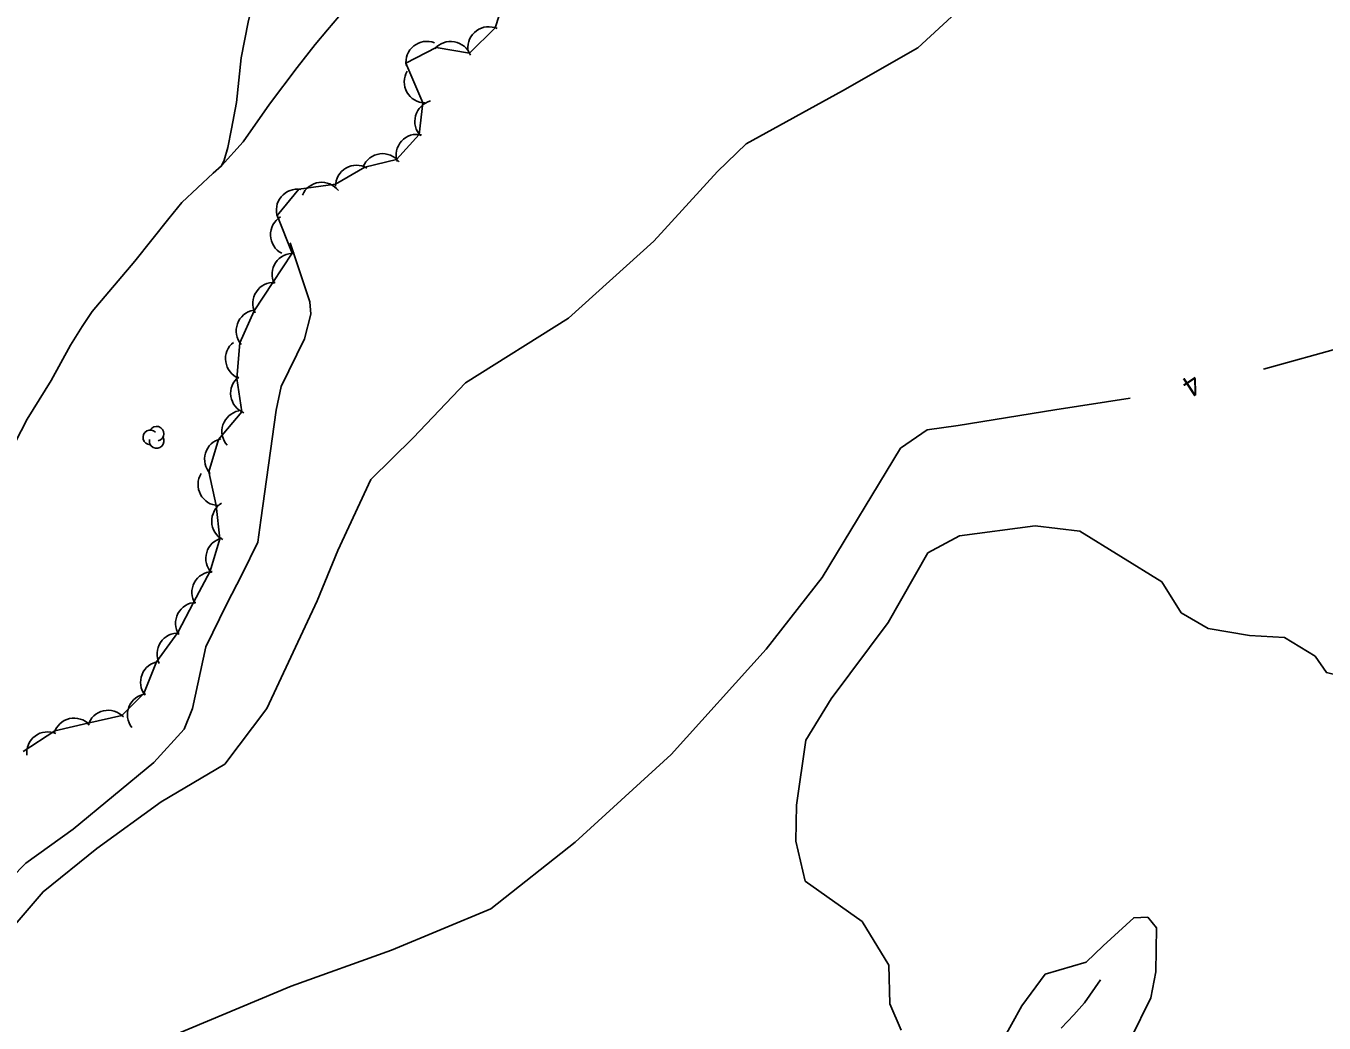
# Model space of a CAD drawing. Extents: x 643342 to 646936, y 5873857 to 5876103.
# Drawn here: x 644900.4 to 645086.4, y 5874417.3 to 5874560.2 of the extents above; entities that cross this region are included whole.
import ezdxf

# ---------------------------------------------------------------- set-up
doc = ezdxf.new("R2010")
doc.units = 0
for name, color, linetype in [('Niveau 2', 7, 'Continuous'), ('Niveau 22', 7, 'Continuous'), ('Niveau 44', 7, 'Continuous')]:
    doc.layers.add(name, color=color, linetype=linetype)

msp = doc.modelspace()

# ---------------------------------------------------------------- linework, layer by layer
at = {"layer": 'Niveau 2'}
for points in [[(645077.7, 5874510.97), (645089.39, 5874514.25), (645098.21, 5874521.23), (645104.55, 5874528.4), (645107.37, 5874537.11), (645109.34, 5874546.11), (645117.52, 5874564.17), (645122.1, 5874572.99), (645130.85, 5874588.01), (645134.74, 5874593.01), (645147.47, 5874604.86), (645154.32, 5874613.24), (645160.03, 5874620.96), (645165.88, 5874628.33), (645170.57, 5874631.23), (645172.38, 5874635.85), (645176.56, 5874643.59), (645182.1, 5874648.57)], [(645168.31, 5874573.93), (645168.27, 5874573.87), (645165.79, 5874571.46), (645159.02, 5874561.45), (645155.45, 5874553.41), (645153.44, 5874546.79), (645149.85, 5874539.11), (645145.87, 5874528.57), (645141.75, 5874521.8), (645134.17, 5874514.09), (645128.28, 5874500.6), (645120.31, 5874490.03), (645114.98, 5874478.69), (645111.19, 5874475.72), (645100.42, 5874471.57), (645088.62, 5874467.05), (645086.71, 5874467.51), (645085.08, 5874469.87), (645080.72, 5874472.53), (645075.7, 5874472.84)], [(645033.6, 5874562.02), (645028.16, 5874557.02), (645017.36, 5874550.84), (645003.58, 5874543.28), (644999.48, 5874539.32), (644990.35, 5874529.34), (644978.11, 5874518.31), (644963.38, 5874509.01), (644955.88, 5874501.15), (644949.79, 5874495.17), (644945.06, 5874485), (644942.13, 5874477.8), (644934.92, 5874462.37), (644928.86, 5874454.37), (644919.76, 5874449.01), (644910.52, 5874442.33), (644902.84, 5874436.11), (644893.32, 5874425.03), (644885.55, 5874412.64)], [(644862.96, 5874331.87), (644868.54, 5874343.25), (644872.82, 5874351.35), (644878.62, 5874361.34), (644883.65, 5874370.44), (644890.35, 5874381.08), (644898.02, 5874394.74), (644909.58, 5874408.43), (644919.08, 5874414.52), (644938.37, 5874422.59), (644952.78, 5874427.72), (644967.01, 5874433.66), (644979.09, 5874443.24), (644992.85, 5874455.77), (645006.44, 5874470.89), (645014.46, 5874481.14), (645025.68, 5874499.65), (645029.5, 5874502.27), (645033.94, 5874502.93), (645047.82, 5874505.17), (645058.6, 5874506.84)], [(645024.03, 5874425.61), (645020.19, 5874431.84), (645012.01, 5874437.65), (645010.67, 5874443.34), (645010.78, 5874448.54), (645012.14, 5874457.85), (645015.73, 5874463.76), (645023.92, 5874474.71), (645029.59, 5874484.66), (645034.13, 5874487.1), (645044.98, 5874488.54), (645051.39, 5874487.79), (645063.13, 5874480.5), (645065.91, 5874476.09), (645069.77, 5874473.81), (645075.7, 5874472.84)], [(645040.11, 5874414.44), (645043.09, 5874419.78), (645046.43, 5874424.31), (645052.31, 5874426.01), (645054.74, 5874428.36), (645059.11, 5874432.38), (645061.1, 5874432.45), (645062.38, 5874430.95), (645062.29, 5874424.63), (645061.54, 5874420.93), (645058.66, 5874415.01)], [(645024.03, 5874425.61), (645024.18, 5874420.07), (645025.8, 5874416.29)]]:
    msp.add_lwpolyline(points, dxfattribs=at)
at = {"layer": 'Niveau 22'}
for points in [[(644898.02, 5874498.92), (644900.58, 5874503.83), (644903.98, 5874509.35), (644906.78, 5874514.43), (644908.44, 5874517.12), (644909.89, 5874519.24), (644916.01, 5874526.45), (644920.84, 5874532.57), (644922.72, 5874534.87), (644927.21, 5874539.05), (644928.41, 5874540.13), (644928.79, 5874540.94), (644929.33, 5874542.75), (644929.86, 5874545.4), (644930.55, 5874549.19), (644931.23, 5874555.58), (644932.21, 5874560.72), (644932.77, 5874562.92), (644934.55, 5874567.88), (644935.58, 5874570.37), (644937.65, 5874574.06)], [(644945.21, 5874561.49), (644943.59, 5874559.6), (644941.84, 5874557.5), (644939.24, 5874554.2), (644935.28, 5874548.94), (644931.53, 5874543.54), (644928.41, 5874540.13)], [(644872.15, 5874408.35), (644881.75, 5874419.98), (644889.76, 5874429.22), (644894.01, 5874433.74), (644900.35, 5874440.23), (644907.17, 5874445.09), (644918.71, 5874454.64), (644923.06, 5874459.41), (644924.24, 5874462.36), (644926.15, 5874471.2), (644929.1, 5874477.28), (644931.36, 5874481.63), (644933.6, 5874486.22), (644934.06, 5874489.35), (644936.25, 5874505.12), (644936.93, 5874508.5), (644940.29, 5874515.33), (644941.2, 5874518.86), (644941.06, 5874520.63), (644938.24, 5874529.1)], [(645054.32, 5874423.49), (645052.05, 5874420.18), (645050.54, 5874418.49), (645048.7, 5874416.59)]]:
    msp.add_lwpolyline(points, dxfattribs=at)
at = {"layer": 'Niveau 44'}
for points in [[(644969.29, 5874565.07), (644967.63, 5874559.89), (644963.94, 5874556.26), (644959.16, 5874557.09), (644954.82, 5874554.81), (644957.23, 5874549.14), (644956.74, 5874544.61), (644953.47, 5874541.03), (644948.96, 5874539.94), (644944.76, 5874537.51), (644939.46, 5874536.77), (644936.36, 5874533.02), (644938.53, 5874527.58), (644935.77, 5874523.41), (644933.09, 5874519.36), (644931.03, 5874514.77)], [(644931.03, 5874514.77), (644930.61, 5874509.67), (644931.33, 5874504.87), (644927.98, 5874500.91), (644926.59, 5874496.26), (644927.63, 5874491.47), (644928.15, 5874486.69), (644926.79, 5874482.04), (644924.4, 5874477.54), (644922.13, 5874473.25), (644919.09, 5874469.03), (644917.27, 5874464.53), (644914.13, 5874461.38), (644909.26, 5874460.26), (644904.53, 5874459.16), (644899.98, 5874456.21)]]:
    msp.add_lwpolyline(points, dxfattribs=at)
for centre, radius, start, end in [((644966.69, 5874557.04), 3, 65.8041, 185.7821), ((644966.69, 5874557.04), 3, 65.8041, 185.7821), ((644966.69, 5874557.04), 3, 65.8041, 185.7821), ((644957.82, 5874554.95), 3, 68.6819, 188.6598), ((644957.82, 5874554.95), 3, 68.6819, 188.6598), ((644957.82, 5874554.95), 3, 68.6819, 188.6598), ((644961.25, 5874554.94), 3, 20.1183, 140.0962), ((644961.25, 5874554.94), 3, 20.1183, 140.0962), ((644961.25, 5874554.94), 3, 20.1183, 140.0962), ((644957.59, 5874552.12), 3, 149.047, 269.0249), ((644957.59, 5874552.12), 3, 149.047, 269.0249), ((644957.59, 5874552.12), 3, 149.047, 269.0249), ((644959.1, 5874546.5), 3, 104.5199, 224.4978), ((644959.1, 5874546.5), 3, 104.5199, 224.4978), ((644959.1, 5874546.5), 3, 104.5199, 224.4978), ((644956.41, 5874541.63), 3, 77.6215, 197.5994), ((644956.41, 5874541.63), 3, 77.6215, 197.5994), ((644956.41, 5874541.63), 3, 77.6215, 197.5994), ((644951.47, 5874538.86), 3, 37.5157, 157.4936), ((644951.47, 5874538.86), 3, 37.5157, 157.4936), ((644951.47, 5874538.86), 3, 37.5157, 157.4936), ((644947.74, 5874537.2), 3, 60.0297, 180.0077), ((644947.74, 5874537.2), 3, 60.0297, 180.0077), ((644947.74, 5874537.2), 3, 60.0297, 180.0077), ((644939.27, 5874533.77), 3, 80.423, 200.4009), ((644939.27, 5874533.77), 3, 80.423, 200.4009), ((644939.27, 5874533.77), 3, 80.423, 200.4009), ((644942.76, 5874534.76), 3, 37.0554, 157.0333), ((644942.76, 5874534.76), 3, 37.0554, 157.0333), ((644942.76, 5874534.76), 3, 37.0554, 157.0333), ((644938.43, 5874530.25), 3, 122.13, 242.108), ((644938.43, 5874530.25), 3, 122.13, 242.108), ((644938.43, 5874530.25), 3, 122.13, 242.108), ((644938.66, 5874524.58), 3, 86.4718, 206.4497), ((644938.66, 5874524.58), 3, 86.4718, 206.4497), ((644938.66, 5874524.58), 3, 86.4718, 206.4497), ((644935.9, 5874520.41), 3, 86.4718, 206.4497), ((644935.9, 5874520.41), 3, 86.4718, 206.4497), ((644935.9, 5874520.41), 3, 86.4718, 206.4497), ((644933.51, 5874516.46), 3, 100.0967, 220.0746), ((644933.51, 5874516.46), 3, 100.0967, 220.0746), ((644933.51, 5874516.46), 3, 100.0967, 220.0746), ((644931.98, 5874512.48), 3, 128.5126, 248.4905), ((644931.98, 5874512.48), 3, 128.5126, 248.4905), ((644931.98, 5874512.48), 3, 128.5126, 248.4905), ((644932.71, 5874507.53), 3, 128.5126, 248.4905), ((644932.71, 5874507.53), 3, 128.5126, 248.4905), ((644932.71, 5874507.53), 3, 128.5126, 248.4905), ((644931.46, 5874502.06), 3, 101.4394, 221.4173), ((644931.46, 5874502.06), 3, 101.4394, 221.4173), ((644931.46, 5874502.06), 3, 101.4394, 221.4173), ((644919.11, 5874501.74), 1.05, 282.2692, 149.7263), ((644918.21, 5874501.21), 1.05, 44.1154, 269.804), ((644919.11, 5874500.69), 1.05, 166.9369, 29.6212), ((644928.98, 5874498.08), 3, 103.2833, 223.2613), ((644928.98, 5874498.08), 3, 103.2833, 223.2613), ((644928.98, 5874498.08), 3, 103.2833, 223.2613), ((644928.04, 5874494.44), 3, 148.1205, 268.0984), ((644928.04, 5874494.44), 3, 148.1205, 268.0984), ((644928.04, 5874494.44), 3, 148.1205, 268.0984), ((644930, 5874489.22), 3, 121.9988, 241.9767), ((644930, 5874489.22), 3, 121.9988, 241.9767), ((644930, 5874489.22), 3, 121.9988, 241.9767), ((644929.16, 5874483.87), 3, 103.6492, 223.6272), ((644929.16, 5874483.87), 3, 103.6492, 223.6272), ((644929.16, 5874483.87), 3, 103.6492, 223.6272), ((644927.16, 5874478.99), 3, 92.1194, 212.0973), ((644927.16, 5874478.99), 3, 92.1194, 212.0973), ((644927.16, 5874478.99), 3, 92.1194, 212.0973), ((644924.82, 5874474.57), 3, 92.1194, 212.0973), ((644924.82, 5874474.57), 3, 92.1194, 212.0973), ((644924.82, 5874474.57), 3, 92.1194, 212.0973), ((644922.16, 5874470.17), 3, 86.5369, 206.5148), ((644922.16, 5874470.17), 3, 86.5369, 206.5148), ((644922.16, 5874470.17), 3, 86.5369, 206.5148), ((644919.81, 5874466.12), 3, 97.9428, 217.9207), ((644919.81, 5874466.12), 3, 97.9428, 217.9207), ((644919.81, 5874466.12), 3, 97.9428, 217.9207), ((644917.93, 5874461.49), 3, 97.9428, 217.9207), ((644917.93, 5874461.49), 3, 97.9428, 217.9207), ((644917.93, 5874461.49), 3, 97.9428, 217.9207), ((644912.16, 5874459.11), 3, 42.9901, 162.968), ((644912.16, 5874459.11), 3, 42.9901, 162.968), ((644912.16, 5874459.11), 3, 42.9901, 162.968), ((644907.29, 5874457.99), 3, 42.9901, 162.968), ((644907.29, 5874457.99), 3, 42.9901, 162.968), ((644907.29, 5874457.99), 3, 42.9901, 162.968), ((644903.49, 5874456.02), 3, 66.673, 186.651), ((644903.49, 5874456.02), 3, 66.673, 186.651), ((644903.49, 5874456.02), 3, 66.673, 186.651)]:
    msp.add_arc(centre, radius, start, end, dxfattribs=at)

# ---------------------------------------------------------------- texts
at = {"layer": 'Niveau 2'}
msp.add_text('4', height=3, rotation=213.4033, dxfattribs=at).set_placement((645067.56, 5874510.52))

doc.saveas('drawing.dxf')
